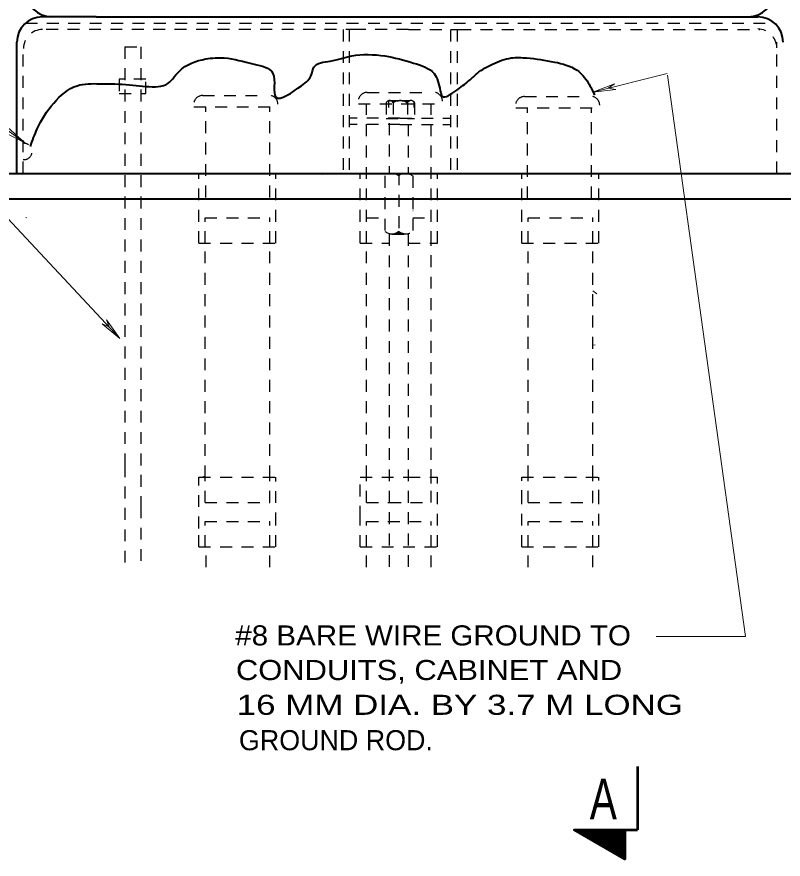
# Model space of a CAD drawing. Extents: x 312583 to 312854, y 144419 to 144597.
# Drawn here: x 312640.47 to 312669.46, y 144495.61 to 144527.49 of the extents above; entities that cross this region are included whole.
import ezdxf
from ezdxf.enums import TextEntityAlignment as Align

# ---------------------------------------------------------------- set-up
doc = ezdxf.new("R2010")
doc.units = 0
doc.header["$LTSCALE"] = 0.3
doc.linetypes.add('SHORT_DASHED', pattern=[2.7, 1.5, -1.2])
doc.layers.add('1', color=7, linetype='Continuous', lineweight=25)
doc.layers.add('2', color=7, linetype='Continuous', lineweight=13)

msp = doc.modelspace()

# ---------------------------------------------------------------- linework, layer by layer
at = {"layer": '1', "lineweight": 40}
for p, q in [((312643.4625, 144527.4927), (312641.4308, 144527.4927)), ((312643.4625, 144527.4927), (312668.5018, 144527.4927)), ((312640.4725, 144521.5664), (312640.4725, 144526.5344)), ((312635.7498, 144521.5664), (312674.0831, 144521.5664)), ((312654.6558, 144521.5664), (312655.1771, 144521.5664)), ((312634.7915, 144520.608), (312666.3475, 144520.608)), ((312666.3475, 144520.608), (312680.7608, 144520.608))]:
    msp.add_line(p, q, dxfattribs=at)
at = {"layer": '1', "linetype": 'SHORT_DASHED'}
for p, q in [((312640.7945, 144527.255), (312669.1381, 144527.255)), ((312652.8081, 144527.0097), (312652.8081, 144521.5664)), ((312653.0458, 144527.0097), (312653.0458, 144521.5664)), ((312656.8791, 144527.0097), (312656.8791, 144521.5664)), ((312657.1245, 144527.0097), (312657.1245, 144521.5664)), ((312669.2225, 144521.5664), (312669.2225, 144526.5344)), ((312640.7101, 144521.5664), (312640.7101, 144526.2814)), ((312644.5588, 144526.358), (312645.1568, 144526.358)), ((312644.5588, 144526.358), (312644.5588, 144510.5264)), ((312645.1568, 144526.358), (312645.1568, 144508.97)), ((312647.4951, 144524.518), (312649.9178, 144524.518)), ((312653.7205, 144524.633), (312656.1431, 144524.633)), ((312653.3908, 144524.2037), (312656.5725, 144524.2037)), ((312653.6975, 144518.929), (312653.6975, 144524.2037)), ((312654.4411, 144524.242), (312654.4411, 144523.644)), ((312654.5408, 144524.058), (312654.5408, 144524.3034)), ((312654.5715, 144524.3264), (312655.3765, 144524.3264)), ((312654.7095, 144524.242), (312654.7095, 144523.644)), ((312655.2461, 144524.242), (312655.2461, 144523.644)), ((312655.4991, 144524.058), (312655.4991, 144524.3034)), ((312655.5145, 144524.242), (312655.5145, 144523.644)), ((312656.1431, 144518.929), (312656.1431, 144524.2037)), ((312659.6775, 144524.4797), (312662.0925, 144524.4797)), ((312647.1655, 144524.0887), (312650.3471, 144524.0887)), ((312647.6178, 144520.6617), (312647.6178, 144524.0887)), ((312650.0328, 144520.6617), (312650.0328, 144524.0887)), ((312659.3478, 144524.0504), (312662.5218, 144524.0504)), ((312659.7925, 144520.6234), (312659.7925, 144524.0504)), ((312662.2075, 144520.6234), (312662.2075, 144524.0504)), ((312654.9625, 144523.6594), (312653.0458, 144523.6594)), ((312654.4411, 144523.644), (312655.5145, 144523.644)), ((312654.9625, 144523.6594), (312656.8791, 144523.6594)), ((312654.9625, 144523.4217), (312653.0458, 144523.4217)), ((312654.5561, 144523.4677), (312654.5561, 144521.5664)), ((312654.9625, 144523.4217), (312656.8791, 144523.4217)), ((312655.2768, 144523.4294), (312655.2768, 144521.5664)), ((312647.3495, 144518.929), (312647.3495, 144521.5664)), ((312650.2705, 144518.929), (312650.2705, 144521.5664)), ((312653.4598, 144518.929), (312653.4598, 144521.5664)), ((312654.3951, 144521.4744), (312654.3951, 144519.3737)), ((312654.5561, 144521.5664), (312655.2768, 144521.5664)), ((312654.9165, 144521.5664), (312654.9165, 144519.274)), ((312655.4455, 144521.4744), (312655.4455, 144519.3737)), ((312656.3808, 144518.929), (312656.3808, 144521.5664)), ((312659.5701, 144518.929), (312659.5701, 144521.5664)), ((312662.4911, 144518.929), (312662.4911, 144521.5664)), ((312647.5871, 144519.8874), (312650.0328, 144519.8874)), ((312647.5871, 144518.929), (312647.5871, 144519.8874)), ((312650.0328, 144518.929), (312650.0328, 144519.8874)), ((312653.6975, 144519.8874), (312654.3951, 144519.8874)), ((312655.4455, 144519.8874), (312656.1431, 144519.8874)), ((312659.8078, 144519.8874), (312662.2535, 144519.8874)), ((312659.8078, 144518.929), (312659.8078, 144519.8874)), ((312662.2535, 144518.929), (312662.2535, 144519.8874)), ((312654.5561, 144519.274), (312654.5561, 144506.6087)), ((312654.6558, 144519.274), (312655.1771, 144519.274)), ((312655.2768, 144519.274), (312655.2768, 144506.6317)), ((312647.3495, 144518.929), (312650.2705, 144518.929)), ((312647.5871, 144510.0664), (312647.5871, 144518.929)), ((312650.0328, 144510.0664), (312650.0328, 144518.929)), ((312653.4598, 144518.929), (312654.5561, 144518.929)), ((312653.6975, 144510.0664), (312653.6975, 144518.929)), ((312655.2768, 144518.929), (312656.3808, 144518.929)), ((312656.1431, 144509.108), (312656.1431, 144518.929)), ((312659.5701, 144518.929), (312662.4911, 144518.929)), ((312644.5588, 144510.5264), (312644.5588, 144506.6624)), ((312647.3495, 144510.0664), (312650.2705, 144510.0664)), ((312647.5871, 144509.108), (312647.5871, 144510.0664)), ((312650.0328, 144509.108), (312650.0328, 144510.0664)), ((312653.6975, 144509.108), (312653.6975, 144510.0664)), ((312656.1431, 144509.8287), (312656.1431, 144510.0664)), ((312656.3808, 144507.429), (312656.3808, 144510.0664)), ((312656.3808, 144509.8287), (312656.3808, 144510.0664)), ((312659.5701, 144510.0664), (312662.4911, 144510.0664)), ((312645.1568, 144508.97), (312645.1568, 144506.6624)), ((312647.5871, 144509.108), (312650.0328, 144509.108)), ((312653.6975, 144509.108), (312654.5561, 144509.108)), ((312654.5561, 144509.108), (312656.1431, 144509.108)), ((312659.8078, 144509.108), (312662.2535, 144509.108)), ((312647.5871, 144508.3874), (312650.0328, 144508.3874)), ((312647.5871, 144507.429), (312647.5871, 144508.3874)), ((312650.0328, 144507.429), (312650.0328, 144508.3874)), ((312653.6975, 144507.429), (312653.6975, 144508.3874)), ((312653.6975, 144508.3874), (312656.1431, 144508.3874)), ((312656.1431, 144507.429), (312656.1431, 144508.3874)), ((312659.8078, 144508.3874), (312662.2535, 144508.3874)), ((312659.8078, 144507.429), (312659.8078, 144508.3874)), ((312662.2535, 144507.429), (312662.2535, 144508.3874)), ((312647.3495, 144507.429), (312650.2705, 144507.429)), ((312647.6331, 144506.6624), (312647.6331, 144507.429)), ((312650.0328, 144506.6624), (312650.0328, 144507.429)), ((312653.4598, 144507.429), (312656.3808, 144507.429)), ((312653.6975, 144506.6624), (312653.6975, 144507.429)), ((312656.1431, 144506.6624), (312656.1431, 144507.429)), ((312659.5701, 144507.429), (312662.4911, 144507.429)), ((312659.8078, 144506.6624), (312659.8078, 144507.429)), ((312662.2535, 144506.6624), (312662.2535, 144507.429))]:
    msp.add_line(p, q, dxfattribs=at)
at = {"layer": '1', "lineweight": 13}
msp.add_line((312655.4455, 144520.148), (312655.4608, 144520.148), dxfattribs=at)
at = {"layer": '1', "lineweight": 53}
for p in [(312663.9478, 144499.1184), (312663.4725, 144496.7264)]:
    msp.add_line(p, (312663.9478, 144496.7264), dxfattribs=at)
at = {"layer": '1', "lineweight": 35}
for p, q in [((312661.5711, 144496.7264), (312661.5711, 144496.711)), ((312661.6018, 144496.7264), (312661.5941, 144496.7034)), ((312661.6325, 144496.7264), (312661.6095, 144496.688)), ((312661.6555, 144496.7264), (312661.6325, 144496.6804)), ((312661.6861, 144496.7264), (312661.6555, 144496.665)), ((312661.7091, 144496.7264), (312661.6708, 144496.6574)), ((312661.7398, 144496.7264), (312661.6938, 144496.642)), ((312661.7705, 144496.7264), (312661.7168, 144496.6344)), ((312661.8011, 144496.7264), (312661.7321, 144496.619)), ((312661.8241, 144496.7264), (312661.7551, 144496.6114)), ((312661.8471, 144496.7264), (312661.7781, 144496.596)), ((312661.8778, 144496.7264), (312661.8011, 144496.5884)), ((312661.9008, 144496.7264), (312661.8165, 144496.573)), ((312661.9315, 144496.7264), (312661.8395, 144496.5577)), ((312661.9621, 144496.7264), (312661.8625, 144496.55)), ((312661.9928, 144496.7264), (312661.8778, 144496.5347)), ((312662.0158, 144496.7264), (312661.9008, 144496.5194)), ((312662.0465, 144496.7264), (312661.9238, 144496.5117)), ((312662.0695, 144496.7264), (312661.9391, 144496.4964)), ((312662.1001, 144496.7264), (312661.9621, 144496.4887)), ((312662.1308, 144496.7264), (312661.9851, 144496.4734)), ((312662.1538, 144496.7264), (312662.0005, 144496.4657)), ((312662.1845, 144496.7264), (312662.0311, 144496.4504)), ((312662.2075, 144496.7264), (312662.0465, 144496.4427)), ((312662.2381, 144496.7264), (312662.0695, 144496.4274)), ((312662.2688, 144496.7264), (312662.0925, 144496.4197)), ((312662.2918, 144496.7264), (312662.1078, 144496.4044)), ((312662.3225, 144496.7264), (312662.1308, 144496.3967)), ((312662.3455, 144496.7264), (312662.1538, 144496.3814)), ((312662.3761, 144496.7264), (312662.1691, 144496.366)), ((312662.3991, 144496.7264), (312662.1921, 144496.3584)), ((312662.4298, 144496.7264), (312662.2151, 144496.343)), ((312662.4605, 144496.7264), (312662.2305, 144496.3277)), ((312662.4911, 144496.7264), (312662.2535, 144496.32)), ((312662.5141, 144496.7264), (312662.2765, 144496.3047)), ((312662.5371, 144496.7264), (312662.2995, 144496.297)), ((312662.5678, 144496.7264), (312662.3148, 144496.2817)), ((312662.5985, 144496.7264), (312662.3378, 144496.274)), ((312662.6215, 144496.7264), (312662.3608, 144496.2587)), ((312662.6521, 144496.7264), (312662.3761, 144496.251)), ((312662.6828, 144496.7264), (312662.3991, 144496.2357)), ((312662.7058, 144496.7264), (312662.4221, 144496.228)), ((312662.7365, 144496.7264), (312662.4375, 144496.2127)), ((312662.7671, 144496.7264), (312662.4605, 144496.205)), ((312662.7901, 144496.7264), (312662.4835, 144496.1897)), ((312662.8208, 144496.7187), (312662.4988, 144496.1744)), ((312662.8438, 144496.7264), (312662.5295, 144496.1667)), ((312662.8745, 144496.7264), (312662.5448, 144496.1514)), ((312662.8975, 144496.7264), (312662.5678, 144496.1437)), ((312662.9281, 144496.7264), (312662.5908, 144496.1284)), ((312662.9588, 144496.7264), (312662.6061, 144496.1207)), ((312662.9895, 144496.7264), (312662.6291, 144496.1054)), ((312663.0125, 144496.7264), (312662.6521, 144496.0977)), ((312663.0355, 144496.7264), (312662.6675, 144496.0824)), ((312663.0661, 144496.7187), (312662.6905, 144496.0747)), ((312663.0968, 144496.7264), (312662.7135, 144496.0594)), ((312663.1198, 144496.7264), (312662.7288, 144496.0517)), ((312663.1505, 144496.7264), (312662.7518, 144496.0364)), ((312663.1811, 144496.7264), (312662.7748, 144496.021)), ((312663.2041, 144496.7264), (312662.7978, 144496.0134)), ((312663.2348, 144496.7264), (312662.8131, 144495.998)), ((312663.2655, 144496.7264), (312662.8361, 144495.9827)), ((312663.2885, 144496.7187), (312662.8591, 144495.975)), ((312663.3191, 144496.7187), (312662.8745, 144495.9597)), ((312663.3421, 144496.7264), (312662.8975, 144495.952)), ((312663.3728, 144496.7264), (312662.9205, 144495.9367)), ((312663.3958, 144496.7264), (312662.9358, 144495.929)), ((312663.4265, 144496.7264), (312662.9588, 144495.9137)), ((312663.4571, 144496.7264), (312662.9818, 144495.906)), ((312663.4725, 144496.7034), (312662.9971, 144495.8907)), ((312663.4725, 144496.6497), (312663.0278, 144495.883)), ((312663.4725, 144496.6114), (312663.0431, 144495.8677)), ((312663.4725, 144496.5577), (312663.0661, 144495.86)), ((312663.4725, 144496.5117), (312663.0891, 144495.8447)), ((312663.4725, 144496.4657), (312663.1045, 144495.8294)), ((312663.4725, 144496.4197), (312663.1275, 144495.8217)), ((312663.4725, 144496.366), (312663.1505, 144495.8064)), ((312663.4725, 144496.32), (312663.1658, 144495.791)), ((312663.4725, 144496.274), (312663.1888, 144495.7834)), ((312663.4725, 144496.2204), (312663.2041, 144495.768)), ((312663.4725, 144496.1744), (312663.2271, 144495.7604)), ((312663.4725, 144496.1284), (312663.2501, 144495.745)), ((312663.4725, 144496.0747), (312663.2655, 144495.7374)), ((312663.4725, 144496.0287), (312663.2961, 144495.722)), ((312663.4725, 144495.9827), (312663.3115, 144495.7144)), ((312663.4725, 144495.9367), (312663.3345, 144495.699)), ((312663.4725, 144495.883), (312663.3575, 144495.6914)), ((312663.4725, 144495.8447), (312663.3728, 144495.676)), ((312663.4725, 144495.791), (312663.3958, 144495.6684)), ((312663.4725, 144495.745), (312663.4188, 144495.653)), ((312663.4725, 144495.6914), (312663.4341, 144495.6377)), ((312663.4725, 144495.6454), (312663.4571, 144495.63))]:
    msp.add_line(p, q, dxfattribs=at)
at = {"layer": '1', "linetype": 'SHORT_DASHED'}
for points in [[(312655.2845, 144527.0097), (312653.3678, 144527.0097), (312641.4385, 144527.0097)], [(312655.2845, 144527.0097), (312657.2011, 144527.0097), (312668.5785, 144527.0097)], [(312654.6098, 144524.3187), (312654.9088, 144524.3187), (312654.8551, 144524.311), (312654.8245, 144524.3034), (312654.7631, 144524.2804), (312654.7095, 144524.242), (312654.6865, 144524.2804), (312654.6635, 144524.2957), (312654.6175, 144524.3187), (312654.8858, 144524.3187), (312654.8091, 144524.3034), (312654.7555, 144524.2804), (312654.7095, 144524.2497), (312654.6711, 144524.2957), (312654.6405, 144524.311), (312654.8475, 144524.3187), (312654.7785, 144524.2957), (312654.7095, 144524.2574), (312654.6558, 144524.311), (312654.8245, 144524.311), (312654.7095, 144524.265), (312654.6635, 144524.311), (312654.8091, 144524.311), (312654.7018, 144524.2727), (312654.6711, 144524.3034), (312654.7861, 144524.3034), (312654.7095, 144524.2804), (312654.6865, 144524.3034), (312654.7555, 144524.3034), (312654.7095, 144524.288), (312654.7018, 144524.2957), (312654.7325, 144524.2957), (312654.7095, 144524.288)], [(312655.3458, 144524.3187), (312655.0468, 144524.3187), (312655.0928, 144524.311), (312655.1311, 144524.3034), (312655.1848, 144524.2804), (312655.2461, 144524.242), (312655.2615, 144524.2804), (312655.2845, 144524.2957), (312655.3305, 144524.3187), (312655.0698, 144524.3187), (312655.1465, 144524.3034), (312655.2001, 144524.2804), (312655.2385, 144524.2497), (312655.2845, 144524.2957), (312655.3151, 144524.311), (312655.1005, 144524.3187), (312655.1771, 144524.2957), (312655.2385, 144524.2574), (312655.2998, 144524.311), (312655.1235, 144524.311), (312655.2461, 144524.265), (312655.2921, 144524.311), (312655.1465, 144524.311), (312655.2461, 144524.2727), (312655.2768, 144524.3034), (312655.1695, 144524.3034), (312655.2461, 144524.2804), (312655.2615, 144524.3034), (312655.1925, 144524.3034), (312655.2385, 144524.288), (312655.2538, 144524.2957), (312655.2231, 144524.2957), (312655.2385, 144524.288)], [(312654.7248, 144521.5664), (312655.1158, 144521.5664), (312655.0698, 144521.551), (312655.0315, 144521.5434), (312654.9855, 144521.528), (312654.9548, 144521.5127), (312654.9241, 144521.482), (312654.9165, 144521.482), (312654.8475, 144521.528), (312654.7785, 144521.551), (312654.7478, 144521.5587), (312655.0851, 144521.5587), (312655.0621, 144521.5587), (312655.0315, 144521.551), (312654.9855, 144521.5357), (312654.9395, 144521.5127), (312654.9318, 144521.4974), (312654.9165, 144521.4897), (312654.8551, 144521.528), (312654.7785, 144521.5587), (312655.0391, 144521.5587), (312654.9778, 144521.5357), (312654.9165, 144521.4974), (312654.8091, 144521.551), (312655.0085, 144521.551), (312654.9165, 144521.4974), (312654.8321, 144521.551), (312654.9931, 144521.551), (312654.9241, 144521.5127), (312654.8628, 144521.5434), (312654.9625, 144521.5434), (312654.9165, 144521.528), (312654.8628, 144521.5357), (312654.8935, 144521.5127), (312654.9088, 144521.5434), (312654.9165, 144521.505), (312654.9395, 144521.5357), (312654.9548, 144521.5357), (312654.9701, 144521.5434)], [(312654.7248, 144519.2817), (312655.1158, 144519.2817), (312655.0698, 144519.2894), (312655.0315, 144519.297), (312654.9855, 144519.32), (312654.9548, 144519.3354), (312654.9241, 144519.3584), (312654.9165, 144519.366), (312654.8475, 144519.32), (312654.7785, 144519.2894), (312654.7478, 144519.2817), (312655.0851, 144519.2817), (312655.0621, 144519.2817), (312655.0315, 144519.2894), (312654.9855, 144519.3047), (312654.9395, 144519.3277), (312654.9318, 144519.343), (312654.9165, 144519.3584), (312654.8551, 144519.3124), (312654.7785, 144519.2894), (312655.0391, 144519.2894), (312654.9778, 144519.3047), (312654.9165, 144519.343), (312654.8091, 144519.2894), (312655.0085, 144519.2894), (312654.9165, 144519.3507), (312654.8321, 144519.297), (312654.9931, 144519.2894), (312654.9241, 144519.3354), (312654.8628, 144519.3047), (312654.9625, 144519.297), (312654.9165, 144519.3124), (312654.8628, 144519.3047), (312654.8935, 144519.3277), (312654.9088, 144519.3047), (312654.9165, 144519.3354), (312654.9395, 144519.3124), (312654.9548, 144519.3124), (312654.9701, 144519.3047)], [(312659.8078, 144509.108), (312659.8078, 144510.0664), (312659.8078, 144518.929)], [(312662.2535, 144509.108), (312662.2535, 144510.0664), (312662.2535, 144518.929)], [(312647.3495, 144507.429), (312647.3495, 144508.1344), (312647.3495, 144510.0664)], [(312650.2705, 144507.429), (312650.2705, 144508.2877), (312650.2705, 144510.0664)], [(312653.4598, 144510.0664), (312655.2768, 144510.0664), (312656.3808, 144510.0664)], [(312653.4598, 144507.429), (312653.4598, 144508.533), (312653.4598, 144510.0664)], [(312659.5701, 144507.429), (312659.5701, 144509.1234), (312659.5701, 144510.0664)], [(312662.4911, 144507.429), (312662.4911, 144509.1387), (312662.4911, 144510.0664)]]:
    msp.add_lwpolyline(points, dxfattribs=at)
msp.add_lwpolyline([(312644.3365, 144525.1314), (312644.3365, 144524.587), (312645.3485, 144524.587), (312645.3485, 144525.1314)], close=True, dxfattribs=at)
at = {"layer": '1', "lineweight": 53}
msp.add_lwpolyline([(312663.4725, 144496.7264), (312663.4725, 144495.6147), (312661.5558, 144496.7264)], close=True, dxfattribs=at)
at = {"layer": '1', "lineweight": 40}
for centre, start, end in [((312641.7873, 144528.451), 180, 270), ((312668.1415, 144528.451), 270, 0), ((312641.4279, 144526.5344), 90, 180), ((312668.5008, 144526.5344), 0, 90)]:
    msp.add_arc(centre, 0.9583, start, end, dxfattribs=at)
at = {"layer": '1', "linetype": 'SHORT_DASHED'}
for centre, radius, start, end in [((312641.4375, 144526.2948), 0.7188, 90, 180), ((312668.5008, 144526.3149), 0.7188, 0, 90), ((312647.5005, 144524.1715), 0.3437, 90.411, 194.26621), ((312649.9996, 144524.1821), 0.3437, 0.411, 104.26621), ((312653.7248, 144524.2894), 0.3437, 90.411, 194.26621), ((312656.224, 144524.2999), 0.3437, 0.411, 104.26621), ((312654.572, 144524.175), 0.1489, 25.60064, 154.39936), ((312654.9749, 144523.8551), 0.4689, 55.04559, 124.95441), ((312655.3779, 144524.175), 0.1489, 25.60064, 154.39936), ((312659.6771, 144524.1331), 0.3437, 90.411, 194.26621), ((312662.1762, 144524.1437), 0.3437, 0.411, 104.26621), ((312654.6552, 144521.1592), 0.4079, 50.00693, 129.99306), ((312655.1796, 144521.1592), 0.4079, 50.00694, 129.99307), ((312654.6552, 144519.6852), 0.4079, 230.00694, 309.99307), ((312655.1796, 144519.6852), 0.4079, 230.00693, 309.99306)]:
    msp.add_arc(centre, radius, start, end, dxfattribs=at)
at = {"layer": '1', "lineweight": 40}
msp.add_spline([(312640.9785, 144522.586), (312641.2391, 144523.253), (312641.8601, 144524.2267), (312642.7495, 144524.886), (312643.6081, 144524.9627), (312644.7351, 144524.9244), (312645.7088, 144524.8477), (312646.0998, 144524.9244), (312646.6058, 144525.4304), (312647.6178, 144525.898), (312648.3155, 144525.9364), (312649.4425, 144525.7064), (312650.1478, 144525.3537), (312650.2628, 144524.4567), (312651.2365, 144524.886), (312651.6198, 144525.3154), (312651.7041, 144525.5837), (312652.3251, 144525.8214), (312653.1378, 144526.013), (312654.3875, 144526.013), (312655.4761, 144525.7447), (312656.2505, 144525.3537), (312656.4881, 144524.6944), (312656.5648, 144524.495), (312657.0708, 144524.6944), (312657.5768, 144525.0777), (312657.8835, 144525.3537), (312658.4661, 144525.7064), (312659.1715, 144525.9364), (312659.7541, 144525.9364), (312660.8045, 144525.783), (312661.6631, 144525.4687), (312662.0848, 144525.001), (312662.3225, 144524.5334)], degree=3, dxfattribs=at)
at = {"layer": '2'}
for p, q in [((312634.6228, 144527.186), (312640.7638, 144522.724)), ((312634.8911, 144525.4534), (312644.3595, 144515.318)), ((312665.0748, 144525.3537), (312662.2611, 144524.6484)), ((312662.2611, 144524.6484), (312663.0815, 144524.955)), ((312663.0815, 144524.955), (312662.8438, 144524.794)), ((312662.2611, 144524.6484), (312663.1351, 144524.748)), ((312663.1351, 144524.748), (312662.8438, 144524.794)), ((312640.7638, 144522.724), (312640.1198, 144523.3067)), ((312640.7638, 144522.724), (312639.9895, 144523.1304)), ((312640.8481, 144519.8874), (312640.8098, 144519.9027)), ((312650.2705, 144519.9487), (312650.2705, 144519.9564)), ((312662.4145, 144517.0124), (312662.2535, 144517.1197)), ((312643.8535, 144516.0234), (312643.9608, 144515.755)), ((312644.3595, 144515.318), (312643.8535, 144516.0234)), ((312643.6925, 144515.8777), (312643.9608, 144515.755)), ((312644.3595, 144515.318), (312643.6925, 144515.8777)), ((312662.2535, 144515.0727), (312662.3531, 144515.0804)), ((312647.5871, 144510.12), (312647.4798, 144510.0664))]:
    msp.add_line(p, q, dxfattribs=at)
for points in [[(312664.6531, 144504.0404), (312668.0341, 144504.0404), (312665.0825, 144525.2847)], [(312652.0491, 144521.5664), (312652.0491, 144521.5204), (312652.1411, 144521.5664)]]:
    msp.add_lwpolyline(points, dxfattribs=at)
at = {"layer": '2', "linetype": 'SHORT_DASHED', "lineweight": 25}
msp.add_arc((312640.7341, 144522.3972), 0.3097, 264.63342, 94.61635, dxfattribs=at)

# ---------------------------------------------------------------- texts
at = {"layer": '1', "width": 0.75}
msp.add_text('A', height=1.533, dxfattribs=at).set_placement((312662.656, 144497.125), align=Align.CENTER)
at = {"layer": '2'}
for s, width, p in [('#8 BARE WIRE GROUND TO', 1.1, (312648.731, 144503.7025)), ('CONDUITS, CABINET AND', 1.15, (312648.7571, 144502.3927)), ('16 MM DIA. BY 3.7 M LONG', 1.3, (312648.7845, 144501.0764))]:
    msp.add_text(s, height=0.76, dxfattribs=dict(at, width=width)).set_placement(p)
msp.add_text('GROUND ROD.', height=0.76, dxfattribs=at).set_placement((312648.8694, 144499.737))

doc.saveas('drawing.dxf')
